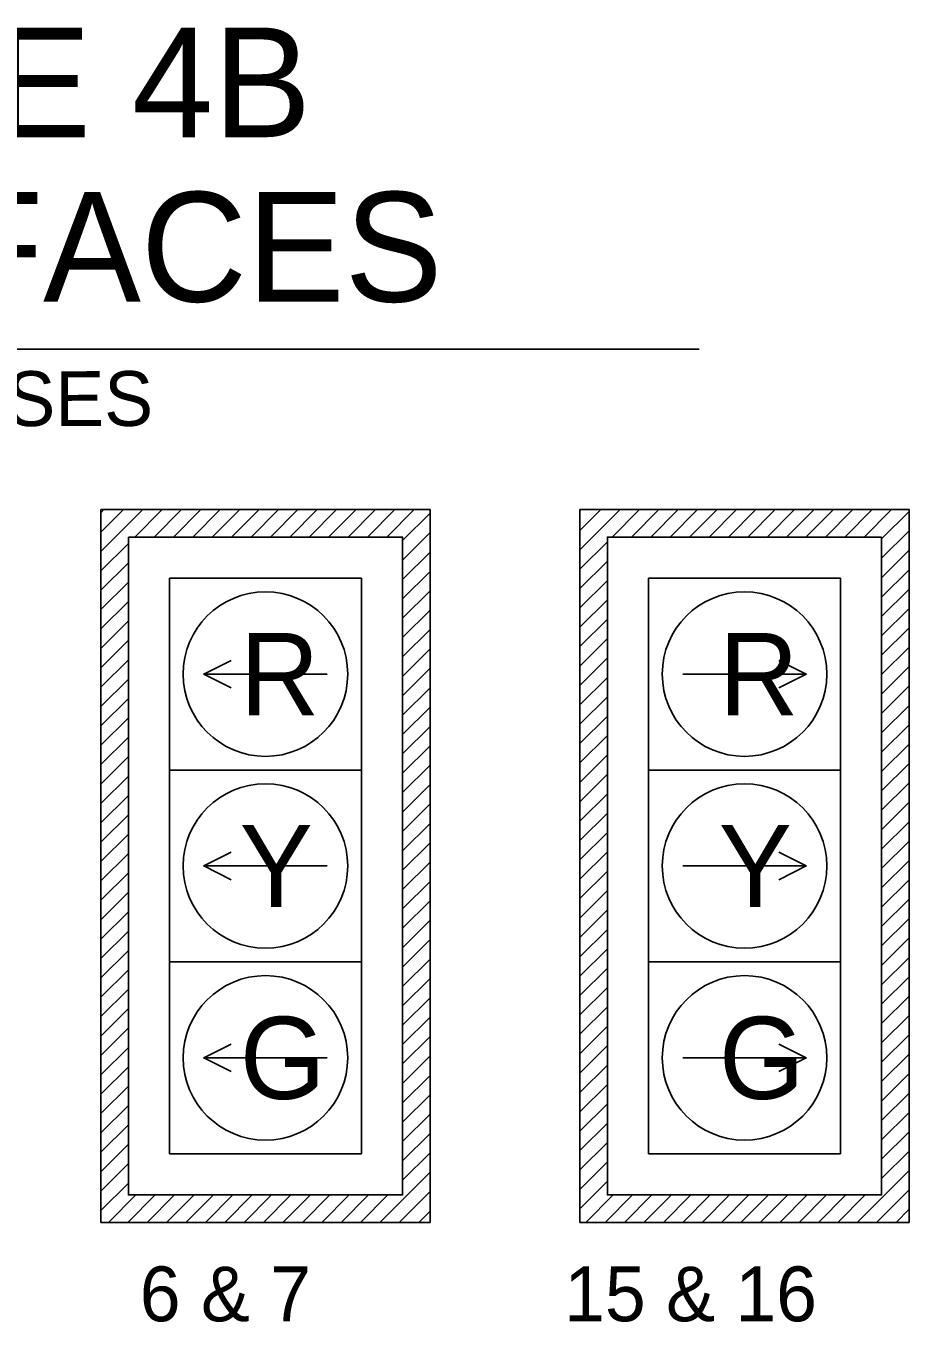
# Model space of a CAD drawing. Extents: x -218554 to 420030, y -565899 to -483460.
# Drawn here: x 419145 to 419209.4, y -565375.2 to -565280.7 of the extents above; entities that cross this region are included whole.
import ezdxf

# ---------------------------------------------------------------- set-up
doc = ezdxf.new("R2010")
doc.units = 0
doc.layers.add('T_Drafting', color=7, linetype='Continuous')
doc.layers.add('T_Notes', color=7, linetype='Continuous')

msp = doc.modelspace()

# ---------------------------------------------------------------- linework, layer by layer
at = {"layer": 'T_Drafting'}
for p, q in [((419150.431, -565315.971), (419174.431, -565315.971)), ((419150.431, -565367.971), (419150.431, -565315.971)), ((419150.431, -565319.02), (419153.481, -565315.971)), ((419150.431, -565317.606), (419152.067, -565315.971)), ((419150.431, -565316.192), (419150.653, -565315.971)), ((419152.895, -565317.971), (419154.895, -565315.971)), ((419154.31, -565317.971), (419156.31, -565315.971)), ((419155.724, -565317.971), (419157.724, -565315.971)), ((419157.138, -565317.971), (419159.138, -565315.971)), ((419158.552, -565317.971), (419160.552, -565315.971)), ((419159.966, -565317.971), (419161.966, -565315.971)), ((419161.381, -565317.971), (419163.381, -565315.971)), ((419162.795, -565317.971), (419164.795, -565315.971)), ((419164.209, -565317.971), (419166.209, -565315.971)), ((419165.623, -565317.971), (419167.623, -565315.971)), ((419167.037, -565317.971), (419169.037, -565315.971)), ((419168.452, -565317.971), (419170.452, -565315.971)), ((419169.866, -565317.971), (419171.866, -565315.971)), ((419171.28, -565317.971), (419173.28, -565315.971)), ((419172.431, -565318.234), (419174.431, -565316.234)), ((419174.431, -565315.971), (419174.431, -565367.971)), ((419209.369, -565315.971), (419185.369, -565315.971)), ((419185.369, -565315.971), (419185.369, -565367.971)), ((419185.369, -565318.896), (419188.294, -565315.971)), ((419185.369, -565317.482), (419186.88, -565315.971)), ((419185.369, -565316.068), (419185.466, -565315.971)), ((419187.709, -565317.971), (419189.709, -565315.971)), ((419189.123, -565317.971), (419191.123, -565315.971)), ((419190.537, -565317.971), (419192.537, -565315.971)), ((419191.951, -565317.971), (419193.951, -565315.971)), ((419193.366, -565317.971), (419195.366, -565315.971)), ((419194.78, -565317.971), (419196.78, -565315.971)), ((419196.194, -565317.971), (419198.194, -565315.971)), ((419197.608, -565317.971), (419199.608, -565315.971)), ((419199.022, -565317.971), (419201.022, -565315.971)), ((419200.437, -565317.971), (419202.437, -565315.971)), ((419201.851, -565317.971), (419203.851, -565315.971)), ((419203.265, -565317.971), (419205.265, -565315.971)), ((419204.679, -565317.971), (419206.679, -565315.971)), ((419206.093, -565317.971), (419208.093, -565315.971)), ((419207.369, -565318.109), (419209.369, -565316.109)), ((419209.369, -565367.971), (419209.369, -565315.971)), ((419172.431, -565319.648), (419174.431, -565317.648)), ((419207.369, -565319.523), (419209.369, -565317.523)), ((419150.431, -565320.435), (419152.431, -565318.435)), ((419185.369, -565320.31), (419187.369, -565318.31)), ((419172.431, -565321.062), (419174.431, -565319.062)), ((419207.369, -565320.938), (419209.369, -565318.938)), ((419150.431, -565321.849), (419152.431, -565319.849)), ((419172.431, -565322.476), (419174.431, -565320.476)), ((419185.369, -565321.724), (419187.369, -565319.724)), ((419207.369, -565322.352), (419209.369, -565320.352)), ((419150.431, -565323.263), (419152.431, -565321.263)), ((419155.431, -565320.971), (419169.431, -565320.971)), ((419155.431, -565320.971), (419155.431, -565334.971)), ((419169.431, -565320.971), (419169.431, -565334.971)), ((419185.369, -565323.139), (419187.369, -565321.139)), ((419204.369, -565320.971), (419190.369, -565320.971)), ((419190.369, -565320.971), (419190.369, -565334.971)), ((419204.369, -565320.971), (419204.369, -565334.971)), ((419172.431, -565323.89), (419174.431, -565321.89)), ((419207.369, -565323.766), (419209.369, -565321.766)), ((419150.431, -565324.677), (419152.431, -565322.677)), ((419172.431, -565325.305), (419174.431, -565323.305)), ((419185.369, -565324.553), (419187.369, -565322.553)), ((419207.369, -565325.18), (419209.369, -565323.18)), ((419150.431, -565326.092), (419152.431, -565324.092)), ((419185.369, -565325.967), (419187.369, -565323.967)), ((419172.431, -565326.719), (419174.431, -565324.719)), ((419207.369, -565326.594), (419209.369, -565324.594)), ((419150.431, -565327.506), (419152.431, -565325.506)), ((419172.431, -565328.133), (419174.431, -565326.133)), ((419185.369, -565327.381), (419187.369, -565325.381)), ((419207.369, -565328.009), (419209.369, -565326.009)), ((419150.431, -565328.92), (419152.431, -565326.92)), ((419185.369, -565328.795), (419187.369, -565326.795)), ((419166.931, -565327.971), (419157.931, -565327.971)), ((419172.431, -565329.547), (419174.431, -565327.547)), ((419192.869, -565327.971), (419201.869, -565327.971)), ((419207.369, -565329.423), (419209.369, -565327.423)), ((419150.431, -565330.334), (419152.431, -565328.334)), ((419172.431, -565330.962), (419174.431, -565328.962)), ((419185.369, -565330.21), (419187.369, -565328.21)), ((419207.369, -565330.837), (419209.369, -565328.837)), ((419150.431, -565331.748), (419152.431, -565329.748)), ((419185.369, -565331.624), (419187.369, -565329.624)), ((419172.431, -565332.376), (419174.431, -565330.376)), ((419185.369, -565333.038), (419187.369, -565331.038)), ((419207.369, -565332.251), (419209.369, -565330.251)), ((419150.431, -565333.163), (419152.431, -565331.163)), ((419172.431, -565333.79), (419174.431, -565331.79)), ((419207.369, -565333.666), (419209.369, -565331.666)), ((419150.431, -565334.577), (419152.431, -565332.577)), ((419185.369, -565334.452), (419187.369, -565332.452)), ((419172.431, -565335.204), (419174.431, -565333.204)), ((419185.369, -565335.867), (419187.369, -565333.867)), ((419207.369, -565335.08), (419209.369, -565333.08)), ((419150.431, -565335.991), (419152.431, -565333.991)), ((419172.431, -565336.618), (419174.431, -565334.618)), ((419207.369, -565336.494), (419209.369, -565334.494)), ((419150.431, -565337.405), (419152.431, -565335.405)), ((419155.431, -565334.971), (419169.431, -565334.971)), ((419155.431, -565334.971), (419155.431, -565348.971)), ((419169.431, -565334.971), (419169.431, -565348.971)), ((419185.369, -565337.281), (419187.369, -565335.281)), ((419204.369, -565334.971), (419190.369, -565334.971)), ((419190.369, -565334.971), (419190.369, -565348.971)), ((419204.369, -565334.971), (419204.369, -565348.971)), ((419172.431, -565338.033), (419174.431, -565336.033)), ((419185.369, -565338.695), (419187.369, -565336.695)), ((419207.369, -565337.908), (419209.369, -565335.908)), ((419150.431, -565338.819), (419152.431, -565336.819)), ((419172.431, -565339.447), (419174.431, -565337.447)), ((419207.369, -565339.322), (419209.369, -565337.322)), ((419150.431, -565340.234), (419152.431, -565338.234)), ((419185.369, -565340.109), (419187.369, -565338.109)), ((419172.431, -565340.861), (419174.431, -565338.861)), ((419185.369, -565341.523), (419187.369, -565339.523)), ((419207.369, -565340.737), (419209.369, -565338.737)), ((419150.431, -565341.648), (419152.431, -565339.648)), ((419172.431, -565342.275), (419174.431, -565340.275)), ((419207.369, -565342.151), (419209.369, -565340.151)), ((419150.431, -565343.062), (419152.431, -565341.062)), ((419185.369, -565342.938), (419187.369, -565340.938)), ((419166.931, -565341.971), (419157.931, -565341.971)), ((419172.431, -565343.689), (419174.431, -565341.689)), ((419185.369, -565344.352), (419187.369, -565342.352)), ((419192.869, -565341.971), (419201.869, -565341.971)), ((419207.369, -565343.565), (419209.369, -565341.565)), ((419150.431, -565344.476), (419152.431, -565342.476)), ((419172.431, -565345.104), (419174.431, -565343.104)), ((419207.369, -565344.979), (419209.369, -565342.979)), ((419150.431, -565345.89), (419152.431, -565343.89)), ((419185.369, -565345.766), (419187.369, -565343.766)), ((419172.431, -565346.518), (419174.431, -565344.518)), ((419185.369, -565347.18), (419187.369, -565345.18)), ((419207.369, -565346.393), (419209.369, -565344.393)), ((419150.431, -565347.305), (419152.431, -565345.305)), ((419172.431, -565347.932), (419174.431, -565345.932)), ((419207.369, -565347.808), (419209.369, -565345.808)), ((419150.431, -565348.719), (419152.431, -565346.719)), ((419185.369, -565348.594), (419187.369, -565346.594)), ((419172.431, -565349.346), (419174.431, -565347.346)), ((419185.369, -565350.009), (419187.369, -565348.009)), ((419207.369, -565349.222), (419209.369, -565347.222)), ((419150.431, -565350.133), (419152.431, -565348.133)), ((419155.431, -565348.971), (419169.431, -565348.971)), ((419155.431, -565348.971), (419155.431, -565362.971)), ((419169.431, -565348.971), (419169.431, -565362.971)), ((419172.431, -565350.761), (419174.431, -565348.761)), ((419204.369, -565348.971), (419190.369, -565348.971)), ((419190.369, -565348.971), (419190.369, -565362.971)), ((419204.369, -565348.971), (419204.369, -565362.971)), ((419207.369, -565350.636), (419209.369, -565348.636)), ((419150.431, -565351.547), (419152.431, -565349.547)), ((419185.369, -565351.423), (419187.369, -565349.423)), ((419172.431, -565352.175), (419174.431, -565350.175)), ((419185.369, -565352.837), (419187.369, -565350.837)), ((419207.369, -565352.05), (419209.369, -565350.05)), ((419150.431, -565352.962), (419152.431, -565350.962)), ((419172.431, -565353.589), (419174.431, -565351.589)), ((419207.369, -565353.465), (419209.369, -565351.465)), ((419150.431, -565354.376), (419152.431, -565352.376)), ((419185.369, -565354.251), (419187.369, -565352.251)), ((419172.431, -565355.003), (419174.431, -565353.003)), ((419185.369, -565355.666), (419187.369, -565353.666)), ((419207.369, -565354.879), (419209.369, -565352.879)), ((419150.431, -565355.79), (419152.431, -565353.79)), ((419172.431, -565356.417), (419174.431, -565354.417)), ((419207.369, -565356.293), (419209.369, -565354.293)), ((419150.431, -565357.204), (419152.431, -565355.204)), ((419185.369, -565357.08), (419187.369, -565355.08)), ((419166.931, -565355.971), (419157.931, -565355.971)), ((419172.431, -565357.832), (419174.431, -565355.832)), ((419185.369, -565358.494), (419187.369, -565356.494)), ((419192.869, -565355.971), (419201.869, -565355.971)), ((419207.369, -565357.707), (419209.369, -565355.707)), ((419150.431, -565358.618), (419152.431, -565356.618)), ((419172.431, -565359.246), (419174.431, -565357.246)), ((419207.369, -565359.121), (419209.369, -565357.121)), ((419150.431, -565360.033), (419152.431, -565358.033)), ((419185.369, -565359.908), (419187.369, -565357.908)), ((419172.431, -565360.66), (419174.431, -565358.66)), ((419185.369, -565361.322), (419187.369, -565359.322)), ((419207.369, -565360.536), (419209.369, -565358.536)), ((419150.431, -565361.447), (419152.431, -565359.447)), ((419172.431, -565362.074), (419174.431, -565360.074)), ((419207.369, -565361.95), (419209.369, -565359.95)), ((419150.431, -565362.861), (419152.431, -565360.861)), ((419185.369, -565362.737), (419187.369, -565360.737)), ((419172.431, -565363.488), (419174.431, -565361.488)), ((419185.369, -565364.151), (419187.369, -565362.151)), ((419207.369, -565363.364), (419209.369, -565361.364)), ((419150.431, -565364.275), (419152.431, -565362.275)), ((419155.431, -565362.971), (419169.431, -565362.971)), ((419172.431, -565364.903), (419174.431, -565362.903)), ((419204.369, -565362.971), (419190.369, -565362.971)), ((419207.369, -565364.778), (419209.369, -565362.778)), ((419150.431, -565365.689), (419152.431, -565363.689)), ((419185.369, -565365.565), (419187.369, -565363.565)), ((419170.778, -565367.971), (419174.431, -565364.317)), ((419185.369, -565366.979), (419187.369, -565364.979)), ((419205.591, -565367.971), (419209.369, -565364.192)), ((419150.431, -565367.104), (419152.431, -565365.104)), ((419150.979, -565367.971), (419152.979, -565365.971)), ((419152.393, -565367.971), (419154.393, -565365.971)), ((419153.807, -565367.971), (419155.807, -565365.971)), ((419155.221, -565367.971), (419157.221, -565365.971)), ((419156.635, -565367.971), (419158.635, -565365.971)), ((419158.05, -565367.971), (419160.05, -565365.971)), ((419159.464, -565367.971), (419161.464, -565365.971)), ((419160.878, -565367.971), (419162.878, -565365.971)), ((419162.292, -565367.971), (419164.292, -565365.971)), ((419163.706, -565367.971), (419165.706, -565365.971)), ((419165.121, -565367.971), (419167.121, -565365.971)), ((419166.535, -565367.971), (419168.535, -565365.971)), ((419167.949, -565367.971), (419169.949, -565365.971)), ((419169.363, -565367.971), (419171.363, -565365.971)), ((419172.192, -565367.971), (419174.431, -565365.731)), ((419185.792, -565367.971), (419187.792, -565365.971)), ((419187.206, -565367.971), (419189.206, -565365.971)), ((419188.62, -565367.971), (419190.62, -565365.971)), ((419190.035, -565367.971), (419192.035, -565365.971)), ((419191.449, -565367.971), (419193.449, -565365.971)), ((419192.863, -565367.971), (419194.863, -565365.971)), ((419194.277, -565367.971), (419196.277, -565365.971)), ((419195.691, -565367.971), (419197.691, -565365.971)), ((419197.106, -565367.971), (419199.106, -565365.971)), ((419198.52, -565367.971), (419200.52, -565365.971)), ((419199.934, -565367.971), (419201.934, -565365.971)), ((419201.348, -565367.971), (419203.348, -565365.971)), ((419202.763, -565367.971), (419204.763, -565365.971)), ((419204.177, -565367.971), (419206.177, -565365.971)), ((419207.005, -565367.971), (419209.369, -565365.607)), ((419173.606, -565367.971), (419174.431, -565367.145)), ((419208.419, -565367.971), (419209.369, -565367.021)), ((419174.431, -565367.971), (419150.431, -565367.971)), ((419185.369, -565367.971), (419209.369, -565367.971))]:
    msp.add_line(p, q, dxfattribs=at)
for points in [[(419152.431, -565317.971), (419172.431, -565317.971), (419172.431, -565365.971), (419152.431, -565365.971)], [(419207.369, -565317.971), (419187.369, -565317.971), (419187.369, -565365.971), (419207.369, -565365.971)]]:
    msp.add_lwpolyline(points, close=True, dxfattribs=at)
for points in [[(419159.931, -565326.971), (419157.931, -565327.971), (419159.931, -565328.971)], [(419199.869, -565326.971), (419201.869, -565327.971), (419199.869, -565328.971)], [(419159.931, -565340.971), (419157.931, -565341.971), (419159.931, -565342.971)], [(419199.869, -565340.971), (419201.869, -565341.971), (419199.869, -565342.971)], [(419159.931, -565354.971), (419157.931, -565355.971), (419159.931, -565356.971)], [(419199.869, -565354.971), (419201.869, -565355.971), (419199.869, -565356.971)]]:
    msp.add_lwpolyline(points, dxfattribs=at)
for centre in [(419162.431, -565327.971), (419197.369, -565327.971), (419162.431, -565341.971), (419197.369, -565341.971), (419162.431, -565355.971), (419197.369, -565355.971)]:
    msp.add_circle(centre, 6, dxfattribs=at)
at = {"layer": 'T_Notes'}
msp.add_line((419095.87, -565304.265), (419194.055, -565304.265), dxfattribs=at)

# ---------------------------------------------------------------- texts
at = {"layer": 'T_Drafting'}
msp.add_text('12" LENSES', height=4, rotation=0.07203, dxfattribs=at).set_placement((419123.796, -565309.899))
for s, p in [('R', (419160.566, -565330.969)), ('R', (419195.504, -565330.969)), ('Y', (419160.542, -565344.969)), ('Y', (419195.48, -565344.969)), ('G', (419160.565, -565358.969)), ('G', (419195.503, -565358.969))]:
    msp.add_text(s, height=5.998, dxfattribs=at).set_placement(p)
at = {"layer": 'T_Notes'}
for s, p in [('STAGE 4B', (419113.451, -565288.796)), ('SIGNAL FACES', (419097.468, -565300.796))]:
    msp.add_text(s, height=8, rotation=360, dxfattribs=at).set_placement(p)
for s, p in [('6 & 7', (419153.265, -565375.192)), ('15 & 16', (419184.212, -565375.192))]:
    msp.add_text(s, height=4, dxfattribs=at).set_placement(p)

doc.saveas('drawing.dxf')
